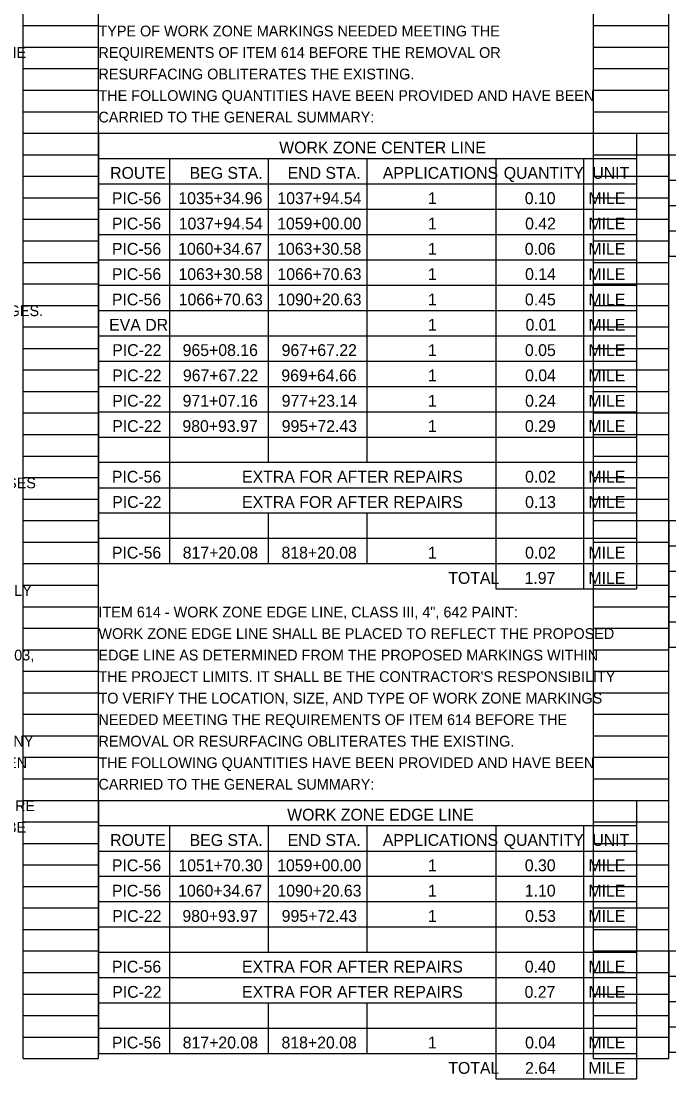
# Model space of a CAD drawing. Extents: x 24172 to 24226.9, y 11011.9 to 11091.2.
# Drawn here: x 24203.76 to 24212.19, y 11012.61 to 11026.37 of the extents above; entities that cross this region are included whole.
import ezdxf

# ---------------------------------------------------------------- set-up
doc = ezdxf.new("R2010")
doc.units = 0
doc.layers.add('SC_Scratch1', color=7, linetype='Continuous')
doc.layers.add('SH_Data', color=7, linetype='Continuous')

msp = doc.modelspace()

# ---------------------------------------------------------------- linework, layer by layer
at = {"layer": 'SH_Data'}
for p, q in [((24203.79, 11012.874), (24203.79, 11033.034)), ((24204.77, 11012.874), (24204.77, 11033.034)), ((24211.21, 11012.874), (24211.21, 11033.034)), ((24212.19, 11012.874), (24212.19, 11033.034)), ((24203.79, 11026.314), (24204.77, 11026.314)), ((24211.21, 11026.314), (24212.19, 11026.314)), ((24203.79, 11026.034), (24204.77, 11026.034)), ((24211.21, 11026.034), (24212.19, 11026.034)), ((24203.79, 11025.754), (24204.77, 11025.754)), ((24211.21, 11025.754), (24212.19, 11025.754)), ((24203.79, 11025.474), (24204.77, 11025.474)), ((24211.21, 11025.474), (24212.19, 11025.474)), ((24203.79, 11025.194), (24204.77, 11025.194)), ((24211.21, 11025.194), (24212.19, 11025.194)), ((24203.79, 11024.914), (24204.77, 11024.914)), ((24204.77, 11024.914), (24211.77, 11024.914)), ((24204.77, 11024.914), (24204.77, 11019.314)), ((24211.21, 11024.914), (24212.19, 11024.914)), ((24211.77, 11024.914), (24211.77, 11018.985)), ((24203.79, 11024.634), (24204.77, 11024.634)), ((24204.77, 11024.585), (24211.77, 11024.585)), ((24205.692, 11024.585), (24205.692, 11019.314)), ((24206.977, 11024.585), (24206.977, 11020.632)), ((24208.261, 11024.585), (24208.261, 11020.632)), ((24209.941, 11024.585), (24209.941, 11018.985)), ((24211.078, 11024.585), (24211.078, 11018.985)), ((24211.21, 11024.634), (24212.19, 11024.634)), ((24212.19, 11024.634), (24216.851, 11024.634)), ((24212.19, 11024.634), (24212.19, 11023.316)), ((24203.79, 11024.354), (24204.77, 11024.354)), ((24204.77, 11024.255), (24211.77, 11024.255)), ((24211.21, 11024.354), (24212.19, 11024.354)), ((24212.19, 11024.305), (24216.851, 11024.305)), ((24203.79, 11024.074), (24204.77, 11024.074)), ((24211.21, 11024.074), (24212.19, 11024.074)), ((24212.19, 11023.975), (24216.851, 11023.975)), ((24204.77, 11023.926), (24211.77, 11023.926)), ((24203.79, 11023.794), (24204.77, 11023.794)), ((24211.21, 11023.794), (24212.19, 11023.794)), ((24204.77, 11023.596), (24211.77, 11023.596)), ((24212.19, 11023.646), (24216.851, 11023.646)), ((24203.79, 11023.514), (24204.77, 11023.514)), ((24211.21, 11023.514), (24212.19, 11023.514)), ((24212.19, 11023.316), (24216.851, 11023.316)), ((24203.79, 11023.234), (24204.77, 11023.234)), ((24204.77, 11023.267), (24211.77, 11023.267)), ((24211.21, 11023.234), (24212.19, 11023.234)), ((24203.79, 11022.954), (24204.77, 11022.954)), ((24204.77, 11022.938), (24211.77, 11022.938)), ((24211.21, 11022.954), (24212.19, 11022.954)), ((24203.79, 11022.674), (24204.77, 11022.674)), ((24204.77, 11022.608), (24211.77, 11022.608)), ((24211.21, 11022.674), (24212.19, 11022.674)), ((24203.79, 11022.394), (24204.77, 11022.394)), ((24211.21, 11022.394), (24212.19, 11022.394)), ((24204.77, 11022.279), (24211.77, 11022.279)), ((24203.79, 11022.114), (24204.77, 11022.114)), ((24211.21, 11022.114), (24212.19, 11022.114)), ((24204.77, 11021.949), (24211.77, 11021.949)), ((24203.79, 11021.834), (24204.77, 11021.834)), ((24211.21, 11021.834), (24212.19, 11021.834)), ((24203.79, 11021.554), (24204.77, 11021.554)), ((24204.77, 11021.62), (24211.77, 11021.62)), ((24211.21, 11021.554), (24212.19, 11021.554)), ((24203.79, 11021.274), (24204.77, 11021.274)), ((24204.77, 11021.291), (24211.77, 11021.291)), ((24211.21, 11021.274), (24212.19, 11021.274)), ((24203.79, 11020.994), (24204.77, 11020.994)), ((24204.77, 11020.961), (24211.77, 11020.961)), ((24211.21, 11020.994), (24212.19, 11020.994)), ((24203.79, 11020.714), (24204.77, 11020.714)), ((24211.21, 11020.714), (24212.19, 11020.714)), ((24204.77, 11020.632), (24211.77, 11020.632)), ((24203.79, 11020.434), (24204.77, 11020.434)), ((24211.21, 11020.434), (24212.19, 11020.434)), ((24204.77, 11020.302), (24211.77, 11020.302)), ((24203.79, 11020.154), (24204.77, 11020.154)), ((24211.21, 11020.154), (24212.19, 11020.154)), ((24203.79, 11019.874), (24204.77, 11019.874)), ((24204.77, 11019.973), (24211.77, 11019.973)), ((24206.977, 11019.973), (24206.977, 11019.314)), ((24208.261, 11019.973), (24208.261, 11019.314)), ((24211.21, 11019.874), (24212.19, 11019.874)), ((24212.19, 11019.874), (24216.851, 11019.874)), ((24212.19, 11019.874), (24212.19, 11018.227)), ((24203.79, 11019.594), (24204.77, 11019.594)), ((24204.77, 11019.644), (24211.77, 11019.644)), ((24211.21, 11019.594), (24212.19, 11019.594)), ((24212.19, 11019.545), (24216.851, 11019.545)), ((24203.79, 11019.314), (24204.77, 11019.314)), ((24204.77, 11019.314), (24211.77, 11019.314)), ((24211.21, 11019.314), (24212.19, 11019.314)), ((24212.19, 11019.215), (24216.851, 11019.215)), ((24203.79, 11019.034), (24204.77, 11019.034)), ((24211.21, 11019.034), (24212.19, 11019.034)), ((24209.941, 11018.985), (24211.77, 11018.985)), ((24212.19, 11018.886), (24216.851, 11018.886)), ((24203.79, 11018.754), (24204.77, 11018.754)), ((24211.21, 11018.754), (24212.19, 11018.754)), ((24203.79, 11018.474), (24204.77, 11018.474)), ((24211.21, 11018.474), (24212.19, 11018.474)), ((24212.19, 11018.556), (24216.851, 11018.556)), ((24203.79, 11018.194), (24204.77, 11018.194)), ((24211.21, 11018.194), (24212.19, 11018.194)), ((24212.19, 11018.227), (24216.851, 11018.227)), ((24203.79, 11017.914), (24204.77, 11017.914)), ((24211.21, 11017.914), (24212.19, 11017.914)), ((24203.79, 11017.634), (24204.77, 11017.634)), ((24211.21, 11017.634), (24212.19, 11017.634)), ((24203.79, 11017.354), (24204.77, 11017.354)), ((24211.21, 11017.354), (24212.19, 11017.354)), ((24203.79, 11017.074), (24204.77, 11017.074)), ((24211.21, 11017.074), (24212.19, 11017.074)), ((24203.79, 11016.794), (24204.77, 11016.794)), ((24211.21, 11016.794), (24212.19, 11016.794)), ((24203.79, 11016.514), (24204.77, 11016.514)), ((24211.21, 11016.514), (24212.19, 11016.514)), ((24203.79, 11016.234), (24204.77, 11016.234)), ((24204.77, 11016.234), (24211.77, 11016.234)), ((24204.77, 11016.234), (24204.77, 11012.94)), ((24211.21, 11016.234), (24212.19, 11016.234)), ((24211.77, 11016.234), (24211.77, 11012.611)), ((24203.79, 11015.954), (24204.77, 11015.954)), ((24204.77, 11015.905), (24211.77, 11015.905)), ((24205.692, 11015.905), (24205.692, 11012.94)), ((24206.977, 11015.905), (24206.977, 11014.258)), ((24208.261, 11015.905), (24208.261, 11014.258)), ((24209.941, 11015.905), (24209.941, 11012.611)), ((24211.078, 11015.905), (24211.078, 11012.611)), ((24211.21, 11015.954), (24212.19, 11015.954)), ((24203.79, 11015.674), (24204.77, 11015.674)), ((24211.21, 11015.674), (24212.19, 11015.674)), ((24204.77, 11015.575), (24211.77, 11015.575)), ((24203.79, 11015.394), (24204.77, 11015.394)), ((24211.21, 11015.394), (24212.19, 11015.394)), ((24204.77, 11015.246), (24211.77, 11015.246)), ((24203.79, 11015.114), (24204.77, 11015.114)), ((24211.21, 11015.114), (24212.19, 11015.114)), ((24204.77, 11014.916), (24211.77, 11014.916)), ((24203.79, 11014.834), (24204.77, 11014.834)), ((24211.21, 11014.834), (24212.19, 11014.834)), ((24203.79, 11014.554), (24204.77, 11014.554)), ((24204.77, 11014.587), (24211.77, 11014.587)), ((24211.21, 11014.554), (24212.19, 11014.554)), ((24203.79, 11014.274), (24204.77, 11014.274)), ((24204.77, 11014.258), (24211.77, 11014.258)), ((24211.21, 11014.274), (24212.19, 11014.274)), ((24212.19, 11014.274), (24216.851, 11014.274)), ((24212.19, 11014.274), (24212.19, 11012.956)), ((24203.79, 11013.994), (24204.77, 11013.994)), ((24204.77, 11013.928), (24211.77, 11013.928)), ((24211.21, 11013.994), (24212.19, 11013.994)), ((24212.19, 11013.945), (24216.851, 11013.945)), ((24203.79, 11013.714), (24204.77, 11013.714)), ((24211.21, 11013.714), (24212.19, 11013.714)), ((24204.77, 11013.599), (24211.77, 11013.599)), ((24206.977, 11013.599), (24206.977, 11012.94)), ((24208.261, 11013.599), (24208.261, 11012.94)), ((24212.19, 11013.615), (24216.851, 11013.615)), ((24203.79, 11013.434), (24204.77, 11013.434)), ((24211.21, 11013.434), (24212.19, 11013.434)), ((24204.77, 11013.269), (24211.77, 11013.269)), ((24212.19, 11013.286), (24216.851, 11013.286)), ((24203.79, 11013.154), (24204.77, 11013.154)), ((24211.21, 11013.154), (24212.19, 11013.154)), ((24203.79, 11012.874), (24204.77, 11012.874)), ((24204.77, 11012.94), (24211.77, 11012.94)), ((24211.21, 11012.874), (24212.19, 11012.874)), ((24212.19, 11012.956), (24216.851, 11012.956)), ((24209.941, 11012.611), (24211.77, 11012.611))]:
    msp.add_line(p, q, dxfattribs=at)

# ---------------------------------------------------------------- texts
at = {"layer": 'SC_Scratch1'}
for s, p in [('TYPE OF WORK ZONE MARKINGS NEEDED MEETING THE ', (24204.77, 11026.174)), ('FROM TRAFFIC. THE CONTRACTOR SHALL, AT THE DIRECTION OF THE ', (24197.35, 11025.894)), ('REQUIREMENTS OF ITEM 614 BEFORE THE REMOVAL OR ', (24204.77, 11025.894)), ('RESURFACING OBLITERATES THE EXISTING.', (24204.77, 11025.614)), ('THE FOLLOWING QUANTITIES HAVE BEEN PROVIDED AND HAVE BEEN ', (24204.77, 11025.334)), ('CARRIED TO THE GENERAL SUMMARY:', (24204.77, 11025.054)), ('THE SIGN SHALL HAVE THE CAPABILITY TO STORE UP TO 99 MESSAGES. ', (24197.35, 11022.534)), ('MESSAGE PHASES SHOULD BE EMPLOYED, ALTHOUGH THREE PHASES ', (24197.35, 11020.294)), ('ACTIVATED, DEACTIVATED, OR MESSAGES CHANGED AUTOMATICALLY ', (24197.35, 11018.894)), ('ITEM 614 - WORK ZONE EDGE LINE, CLASS III, 4", 642 PAINT:', (24204.77, 11018.614)), ('WORK ZONE EDGE LINE SHALL BE PLACED TO REFLECT THE PROPOSED ', (24204.77, 11018.334)), ('THE CONTRACTOR, IN ACCORDANCE WITH THE PROVISIONS OF 614.03, ', (24197.35, 11018.054)), ('EDGE LINE AS DETERMINED FROM THE PROPOSED MARKINGS WITHIN ', (24204.77, 11018.054)), ("THE PROJECT LIMITS. IT SHALL BE THE CONTRACTOR'S RESPONSIBILITY ", (24204.77, 11017.774)), ('TO VERIFY THE LOCATION, SIZE, AND TYPE OF WORK ZONE MARKINGS ', (24204.77, 11017.494)), ('NEEDED MEETING THE REQUIREMENTS OF ITEM 614 BEFORE THE ', (24204.77, 11017.214)), ('PCMS TO ENSURE PROMPT SERVICE IN THE EVENT OF A FAILURE. ANY ', (24197.35, 11016.934)), ('REMOVAL OR RESURFACING OBLITERATES THE EXISTING.', (24204.77, 11016.934)), ('FAILURE SHALL NOT RESULT IN AN ORDER TO STOP WORK AND OPEN ', (24197.35, 11016.654)), ('THE FOLLOWING QUANTITIES HAVE BEEN PROVIDED AND HAVE BEEN ', (24204.77, 11016.654)), ('CARRIED TO THE GENERAL SUMMARY:', (24204.77, 11016.374)), ('APPROPRIATE ACTION TO SAFELY CONTROL TRAFFIC AND THE ENTIRE ', (24197.35, 11016.094)), ('COST TO CONTROL TRAFFIC ACCRUED BY THE DEPARTMENT WILL BE ', (24197.35, 11015.814))]:
    msp.add_text(s, height=0.14, dxfattribs=at).set_placement(p)
at = {"layer": 'SH_Data'}
for s, p in [('WORK ZONE CENTER LINE', (24207.121, 11024.651)), ('ROUTE', (24204.922, 11024.321)), ('BEG STA.', (24205.956, 11024.321)), ('END STA.', (24207.231, 11024.321)), ('APPLICATIONS', (24208.469, 11024.321)), ('QUANTITY', (24210.042, 11024.321)), ('UNIT', (24211.195, 11024.321)), ('PIC-56', (24204.945, 11023.992)), ('1035+34.96', (24205.809, 11023.992)), ('1037+94.54', (24207.098, 11023.992)), ('1', (24209.056, 11023.992)), ('0.10', (24210.316, 11023.992)), ('MILE', (24211.144, 11023.992)), ('PIC-56', (24204.945, 11023.662)), ('1037+94.54', (24205.814, 11023.662)), ('1059+00.00', (24207.095, 11023.662)), ('1', (24209.056, 11023.662)), ('0.42', (24210.32, 11023.662)), ('MILE', (24211.144, 11023.662)), ('PIC-56', (24204.945, 11023.333)), ('1060+34.67', (24205.807, 11023.333)), ('1063+30.58', (24207.095, 11023.333)), ('1', (24209.056, 11023.333)), ('0.06', (24210.316, 11023.333)), ('MILE', (24211.144, 11023.333)), ('PIC-56', (24204.945, 11023.004)), ('1063+30.58', (24205.811, 11023.004)), ('1066+70.63', (24207.098, 11023.004)), ('1', (24209.056, 11023.004)), ('0.14', (24210.32, 11023.004)), ('MILE', (24211.144, 11023.004)), ('PIC-56', (24204.945, 11022.674)), ('1066+70.63', (24205.814, 11022.674)), ('1090+20.63', (24207.098, 11022.674)), ('1', (24209.056, 11022.674)), ('0.45', (24210.318, 11022.674)), ('MILE', (24211.144, 11022.674)), ('EVA DR', (24204.909, 11022.345)), ('1', (24209.056, 11022.345)), ('0.01', (24210.326, 11022.345)), ('MILE', (24211.144, 11022.345)), ('PIC-22', (24204.949, 11022.015)), ('965+08.16', (24205.865, 11022.015)), ('967+67.22', (24207.153, 11022.015)), ('1', (24209.056, 11022.015)), ('0.05', (24210.318, 11022.015)), ('MILE', (24211.144, 11022.015)), ('PIC-22', (24204.949, 11021.686)), ('967+67.22', (24205.869, 11021.686)), ('969+64.66', (24207.149, 11021.686)), ('1', (24209.056, 11021.686)), ('0.04', (24210.32, 11021.686)), ('MILE', (24211.144, 11021.686)), ('PIC-22', (24204.949, 11021.356)), ('971+07.16', (24205.865, 11021.356)), ('977+23.14', (24207.154, 11021.356)), ('1', (24209.056, 11021.356)), ('0.24', (24210.32, 11021.356)), ('MILE', (24211.144, 11021.356)), ('PIC-22', (24204.949, 11021.027)), ('980+93.97', (24205.862, 11021.027)), ('995+72.43', (24207.154, 11021.027)), ('1', (24209.056, 11021.027)), ('0.29', (24210.318, 11021.027)), ('MILE', (24211.144, 11021.027)), ('PIC-56', (24204.945, 11020.368)), ('EXTRA FOR AFTER REPAIRS', (24206.638, 11020.368)), ('0.02', (24210.32, 11020.368)), ('MILE', (24211.144, 11020.368)), ('PIC-22', (24204.949, 11020.039)), ('EXTRA FOR AFTER REPAIRS', (24206.638, 11020.039)), ('0.13', (24210.32, 11020.039)), ('MILE', (24211.144, 11020.039)), ('PIC-56', (24204.945, 11019.38)), ('817+20.08', (24205.866, 11019.38)), ('818+20.08', (24207.151, 11019.38)), ('1', (24209.056, 11019.38)), ('0.02', (24210.32, 11019.38)), ('MILE', (24211.144, 11019.38)), ('TOTAL', (24209.321, 11019.051)), ('1.97', (24210.313, 11019.051)), ('MILE', (24211.144, 11019.051)), ('WORK ZONE EDGE LINE', (24207.225, 11015.971)), ('ROUTE', (24204.922, 11015.641)), ('BEG STA.', (24205.956, 11015.641)), ('END STA.', (24207.231, 11015.641)), ('APPLICATIONS', (24208.469, 11015.641)), ('QUANTITY', (24210.042, 11015.641)), ('UNIT', (24211.195, 11015.641)), ('PIC-56', (24204.945, 11015.312)), ('1051+70.30', (24205.81, 11015.312)), ('1059+00.00', (24207.095, 11015.312)), ('1', (24209.056, 11015.312)), ('0.30', (24210.316, 11015.312)), ('MILE', (24211.144, 11015.312)), ('PIC-56', (24204.945, 11014.982)), ('1060+34.67', (24205.807, 11014.982)), ('1090+20.63', (24207.098, 11014.982)), ('1', (24209.056, 11014.982)), ('1.10', (24210.316, 11014.982)), ('MILE', (24211.144, 11014.982)), ('PIC-22', (24204.949, 11014.653)), ('980+93.97', (24205.862, 11014.653)), ('995+72.43', (24207.154, 11014.653)), ('1', (24209.056, 11014.653)), ('0.53', (24210.32, 11014.653)), ('MILE', (24211.144, 11014.653)), ('PIC-56', (24204.945, 11013.994)), ('EXTRA FOR AFTER REPAIRS', (24206.638, 11013.994)), ('0.40', (24210.316, 11013.994)), ('MILE', (24211.144, 11013.994)), ('PIC-22', (24204.949, 11013.665)), ('EXTRA FOR AFTER REPAIRS', (24206.638, 11013.665)), ('0.27', (24210.313, 11013.665)), ('MILE', (24211.144, 11013.665)), ('PIC-56', (24204.945, 11013.006)), ('817+20.08', (24205.866, 11013.006)), ('818+20.08', (24207.151, 11013.006)), ('1', (24209.056, 11013.006)), ('0.04', (24210.32, 11013.006)), ('MILE', (24211.144, 11013.006)), ('TOTAL', (24209.321, 11012.676)), ('2.64', (24210.32, 11012.676)), ('MILE', (24211.144, 11012.676))]:
    msp.add_text(s, height=0.154, dxfattribs=at).set_placement(p)

doc.saveas('drawing.dxf')
